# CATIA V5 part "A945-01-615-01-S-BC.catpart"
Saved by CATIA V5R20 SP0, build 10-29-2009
Part number: A945-01-615-01-S-BC
Source: Unknown
Property "ARTICLENO": "A945-01-615-01-S-BC"
Property "B": "65.000"
Property "BOMINFO": "A945-01-615-01-S-BC"
Property "CODE": "A945-01-615-01-S-BC"
Property "D1": "20.000"
Property "D2": "13.500"
Property "D5": "16.000"
Property "D6": "12.000"
Property "H": "47.000"
Property "H1": "34.000"
Property "H2": "35.000"
Property "H3": "18.000"
Property "L1": "150.000"
Property "L2": "25.000"
Property "L3": "0.000"
Property "L4": "100.000"
Property "L5": "55.000"
Property "L6": "45.000"
Property "LINA": "A945-01-615-01-S-BC"
Property "N": "1.000"
Property "NB": "A945-01-615-01-S-BC"
Property "NBSYN": " $CODE."
Property "NN": "A945-01"
Property "NT": "v driver sets replaceable inserts pisitive return"
Property "SUPPLIER": "CF"
Property "Z": "65.000"
Bounding box of the stored display mesh (mm): x -5049.207 to 0, y -575.36 to 0, z 0 to 150
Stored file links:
  C:\Users\Utente\Desktop\3D files A945-01\A945-01-615-01-S-BC.catpart
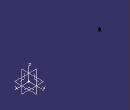
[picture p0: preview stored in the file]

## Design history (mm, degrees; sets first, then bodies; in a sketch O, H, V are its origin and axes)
AxisSystem1: origin (0, 0, 0), X (1, 0, 0), Y (0, 1, 0), Z (0, 0, 1)
Body1 "Geometry.1" (main body)
  Solid1 "A945-01-615-01-S-BC.catpart": solid without history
